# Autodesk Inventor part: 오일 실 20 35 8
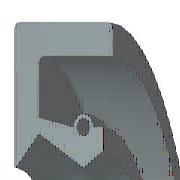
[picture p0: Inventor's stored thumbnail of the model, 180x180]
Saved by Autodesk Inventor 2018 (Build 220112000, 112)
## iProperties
IsCustomPart: 0
Created: 2018-09
Part Number: 오일 실 20 35 8
Material: 고무
Description: 오일-실
Document SubType Name: Modeling
Standard: KS B 2804
Standards Organization: KS
Language: ko-KR
Size Designation: D - 20 35 8
Categories: <MemberInstance><Categories><Category DisplayName="샤프트 부품" InternalName="7f7aeb1f-a693-4053-b835-cee3144e0d98" Mnemonic="SHFT"><Category DisplayName="실링" Intern
Density: 0.93 g/cm^3
Mass: 2.54606 g
Surface Area: 35.9421 cm^2
Volume: 2.7377 cm^3
Appearance: 보라색
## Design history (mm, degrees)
revolve "본체" stored, may be unused: angle "d17" = 90 deg
revolve "스프링1" stored, may be unused: angle "d18" = 90 deg
body "Solid1"
sketch "스케치1"
  geometry: L1 (0, 17.5)-(8, 17.5); L2 (8, 15.75)-(1.75, 15.75); L3 (1.75, 11.75)-(4.9, 10); L4 (4.9, 10)-(0, 10); L5 (0, 0)-(9.586, 0) reference; L6 (4.9, 10)-(6.3, 10.875); L7 (0, 18)-(0, -3) reference; L8 (-1.941, 0)-(11.507, 0) reference; L9 (4.2, 12.1)-(1.75, 12.71); L10 (1.75, 12.71)-(1.75, 15.75); L11 (0, 17.5)-(0, 10.088); L12 (4.9, 10)-(0, 10); L13 (1.75, 11.75)-(0.152, 10.028); L14 (8, 17.5)-(8, 15.75); L15 (5.6, 12.1)-(6.3, 12.1); L16 (6.3, 12.1)-(6.3, 10.875); C1 r 0.455 at (4.9, 12.1); A1 r 0.7 centre (4.9, 12.1) between (5.6, 12.1) and (4.2, 12.1); A2 r 0.088 centre (0.088, 10.088) between (0, 10.088) and (0.152, 10.028); 1 further point
  constraints: 28 end point, 5 horizontal alignment, 5 point on line, 4 point on circle, 4 vertical alignment, 3 centre point, 3 tangent, 2 collinear, 2 horizontal, 2 perpendicular, 1 coincident, 1 parallel
  dimensions: "d0" = 35 diameter of L1 L5 (= SD2); "d1" = 1.75 distance of L1.end L2.start (= SD); "d2" = 0.91 diameter of C1 (= SPDI); "d3" = 1.4 diameter of A1 (= SPDA); "d4" = 20 diameter of L3.end L5 (= NND); "d5" = 23.5 diameter of L3.start L5 (= TKDM); "d7" = 25.42 diameter of L9.end L5 (= TKDM + 0.24 x SWDT); "d8" = 1.75 distance between parallel lines of L11 L10 (= SD); "d9" = 4.9 distance from line of L11 C1.centre (= SPDST); "d10" = 24.2 diameter of C1.centre L5 (= HLDM); "d11" = 0.0875 radius of A2 (= 0.25 x LAB); "d12" = 6.3 distance between parallel lines of L11 L16 (= SDI); "d13" = 21.75 diameter of L6.end L5 (= ABDM); "d14" = 8 distance from line of L11 L1.end (= SWDT)
fillet "모깎기1" dims "d6" = 0.3 (= RR)
other parameters: "SD2" = 35 [user parameter; used in 1 equation term], "SWDT" = 8 [user parameter; used in 2 equation terms], "RR" = 0.3 [user parameter; used in 1 equation term], "SD" = 1.75 [user parameter; used in 2 equation terms], "NND" = 20 [user parameter; used in 1 equation term], "SPDA" = 1.4 [user parameter; used in 1 equation term], "SPDI" = 0.91 [user parameter; used in 1 equation term], "TKDM" = 23.5 [user parameter; used in 2 equation terms], "HLDM" = 24.2 [user parameter; used in 1 equation term], "ABDM" = 21.75 [user parameter; used in 1 equation term], "SDI" = 6.3 [user parameter; used in 1 equation term], "SPDST" = 4.9 [user parameter; used in 1 equation term], "LAB" = 0.35 [user parameter; used in 1 equation term], "d15" = 0, "d16" = 0, "d19" = 0
